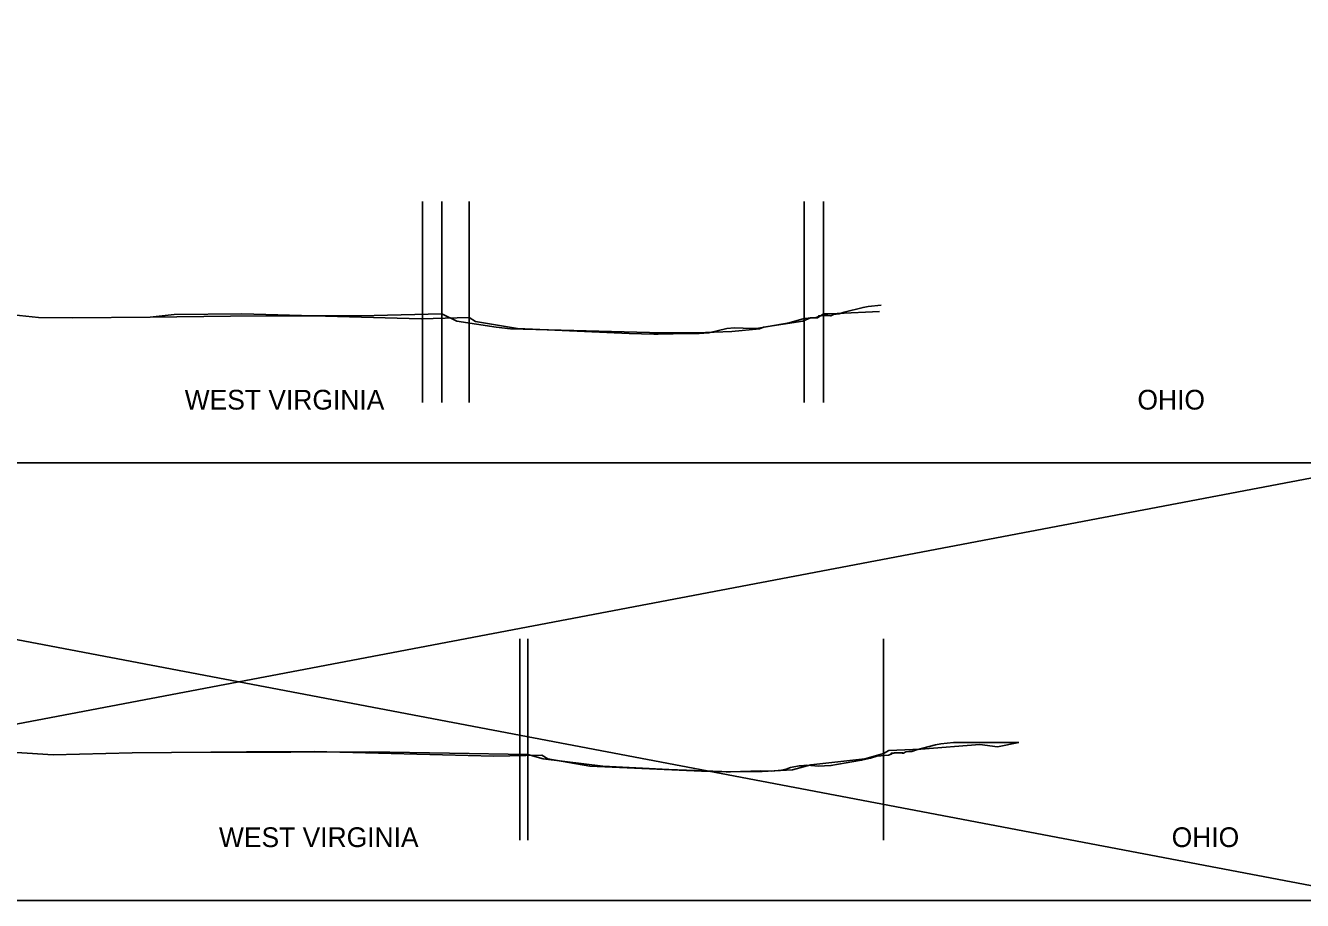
# Model space of a CAD drawing. Extents: x -9489 to 16720, y -4790 to 1662.
# Drawn here: x 2806 to 7653, y -4790 to -1466 of the extents above; entities that cross this region are included whole.
import ezdxf

# ---------------------------------------------------------------- set-up
doc = ezdxf.new("R2010")
doc.units = 0
for name, color, linetype in [('MD_P_Surface_Finished_Grade', 7, 'Continuous'), ('PF_P_Grade_Line', 7, 'Continuous'), ('PF_X_Ground_Line', 7, 'Continuous'), ('SC_Scratch1', 7, 'Continuous')]:
    doc.layers.add(name, color=color, linetype=linetype)

msp = doc.modelspace()

# ---------------------------------------------------------------- linework, layer by layer
at = {"layer": 'MD_P_Surface_Finished_Grade'}
for p, q in [((4386.4, -2134.8), (4386.4, -2898.7)), ((5834.4, -2134.8), (5834.4, -2898.7)), ((4712.4, -3796.7), (4712.4, -4560.6)), ((6062.4, -3796.7), (6062.4, -4560.6))]:
    msp.add_line(p, q, dxfattribs=at)
at = {"layer": 'PF_P_Grade_Line'}
for p, q in [((4312.4, -2134.8), (4312.4, -2898.7)), ((4490.2, -2134.8), (4490.2, -2898.7)), ((5761.8, -2134.8), (5761.8, -2898.7)), ((3370.2, -2563.6), (3278.4, -2574.2)), ((-752.6, -3128.2), (7983.7, -4790.1)), ((-752.6, -4790.1), (7983.7, -3128.2)), ((4682.4, -3796.7), (4682.4, -4560.6)), ((6328.8, -4190.1), (6576.4, -4190.1)), ((3645.2, -4225.4), (3509.4, -4227.1))]:
    msp.add_line(p, q, dxfattribs=at)
at = {"layer": 'PF_X_Ground_Line'}
for points in [[(5863.9, -2568.8), (5860.4, -2567.7), (5857.4, -2567.4), (5843.1, -2567.2), (5828.5, -2567.4), (5816.9, -2568.6), (5816.6, -2572.2)], [(6138.9, -4230.7), (6135.4, -4229.5), (6132.4, -4229.3), (6118.1, -4229), (6103.5, -4229.3), (6091.9, -4230.4), (6091.6, -4234.1)]]:
    msp.add_lwpolyline(points, dxfattribs=at)
at = {"layer": 'SC_Scratch1'}
for points in [[(-752.6, -1466.4), (-752.6, -3128.2), (7983.7, -3128.2)], [(2758.4, -2565.2), (2855.4, -2575.7), (2984.4, -2577.2), (3278.4, -2574.2), (3584.4, -2570.2), (3783.4, -2569.2), (4077.4, -2568.7), (4386.4, -2561.2), (4443.4, -2589.2), (4592.9, -2612.2), (4647.4, -2618.2), (5222.4, -2633.2), (5352.4, -2634.2), (5487.4, -2628.2), (5592.4, -2618.2), (5606.9, -2612.2), (5756.4, -2589.2), (5785.4, -2576.2), (5812.4, -2576.2), (5834.4, -2561.2), (5851.4, -2561.2), (5887.4, -2560.2), (6047.4, -2553.2)], [(6053.8, -2528.2), (6004.9, -2533.6), (5985.3, -2537), (5913.1, -2555.5), (5894.7, -2562.2), (5883.3, -2562.3), (5873, -2563.7), (5863.3, -2569.2), (5859, -2568.3), (5857.4, -2567.8), (5843.1, -2567.4), (5828.5, -2568), (5821.2, -2570.3), (5816.6, -2572.2), (5807, -2576.1), (5761.8, -2579.8), (5704.4, -2595.7), (5588.1, -2615.7), (5563.2, -2617.3), (5497, -2614.5), (5468.1, -2617), (5400.1, -2633.8), (5363.1, -2636.8), (5322.1, -2635.8), (5207.4, -2639.3), (5190.6, -2639.2), (5096.8, -2636.7), (4673.5, -2617.7), (4513.7, -2590.3), (4490.2, -2575.9), (4308.2, -2580.2), (3626.5, -2562.1), (3370.2, -2563.6)], [(-752.6, -3128.2), (-752.6, -4790.1), (7983.7, -4790.1)], [(2613.4, -4218.1), (2911.4, -4237.1), (3210.4, -4229.1), (3509.4, -4227.1), (3812.4, -4226.1), (4112.4, -4225.6), (4415.4, -4230.6), (4712.4, -4235.1), (4771.4, -4251.6), (4997.4, -4280.1), (5247.4, -4293.1), (5482.4, -4301.1), (5602.4, -4300.1), (5717.4, -4294.1), (5787.4, -4275.1), (5992.4, -4251.6), (6062.4, -4232.1), (6082.4, -4220.1), (6204.4, -4215.1), (6428.4, -4198.1), (6495.4, -4206.1), (6576.4, -4190.1)], [(6328.8, -4190.1), (6279.9, -4195.4), (6260.3, -4198.8), (6188.1, -4217.4), (6169.7, -4224.1), (6158.3, -4224.1), (6148, -4225.6), (6138.3, -4231.1), (6134, -4230.2), (6132.4, -4229.6), (6118.1, -4229.3), (6103.5, -4229.9), (6096.2, -4232.2), (6091.6, -4234.1), (6082, -4238), (6036.8, -4241.7), (6013.3, -4250.1), (5979.4, -4257.5), (5863.1, -4277.5), (5838.2, -4279.2), (5816.6, -4280.4), (5772, -4276.4), (5760.7, -4276.9), (5753.5, -4278.9), (5743.1, -4278.9), (5709.8, -4284.9), (5693.5, -4291), (5675.1, -4295.6), (5638.1, -4298.7), (5597.1, -4297.6), (5482.4, -4301.1), (5465.6, -4301), (5371.8, -4298.6), (4948.5, -4279.5), (4788.7, -4252.1), (4765.2, -4237.7), (4583.2, -4242.1), (3901.5, -4224), (3645.2, -4225.4)]]:
    msp.add_lwpolyline(points, dxfattribs=at)

# ---------------------------------------------------------------- texts
at = {"layer": 'MD_P_Surface_Finished_Grade'}
for s, p in [('WEST VIRGINIA', (3410.1, -2925.3)), ('OHIO', (7026.6, -2925.3)), ('WEST VIRGINIA', (3540.1, -4587.2)), ('OHIO', (7156.6, -4587.2))]:
    msp.add_text(s, height=75, dxfattribs=at).set_placement(p)

doc.saveas('drawing.dxf')
